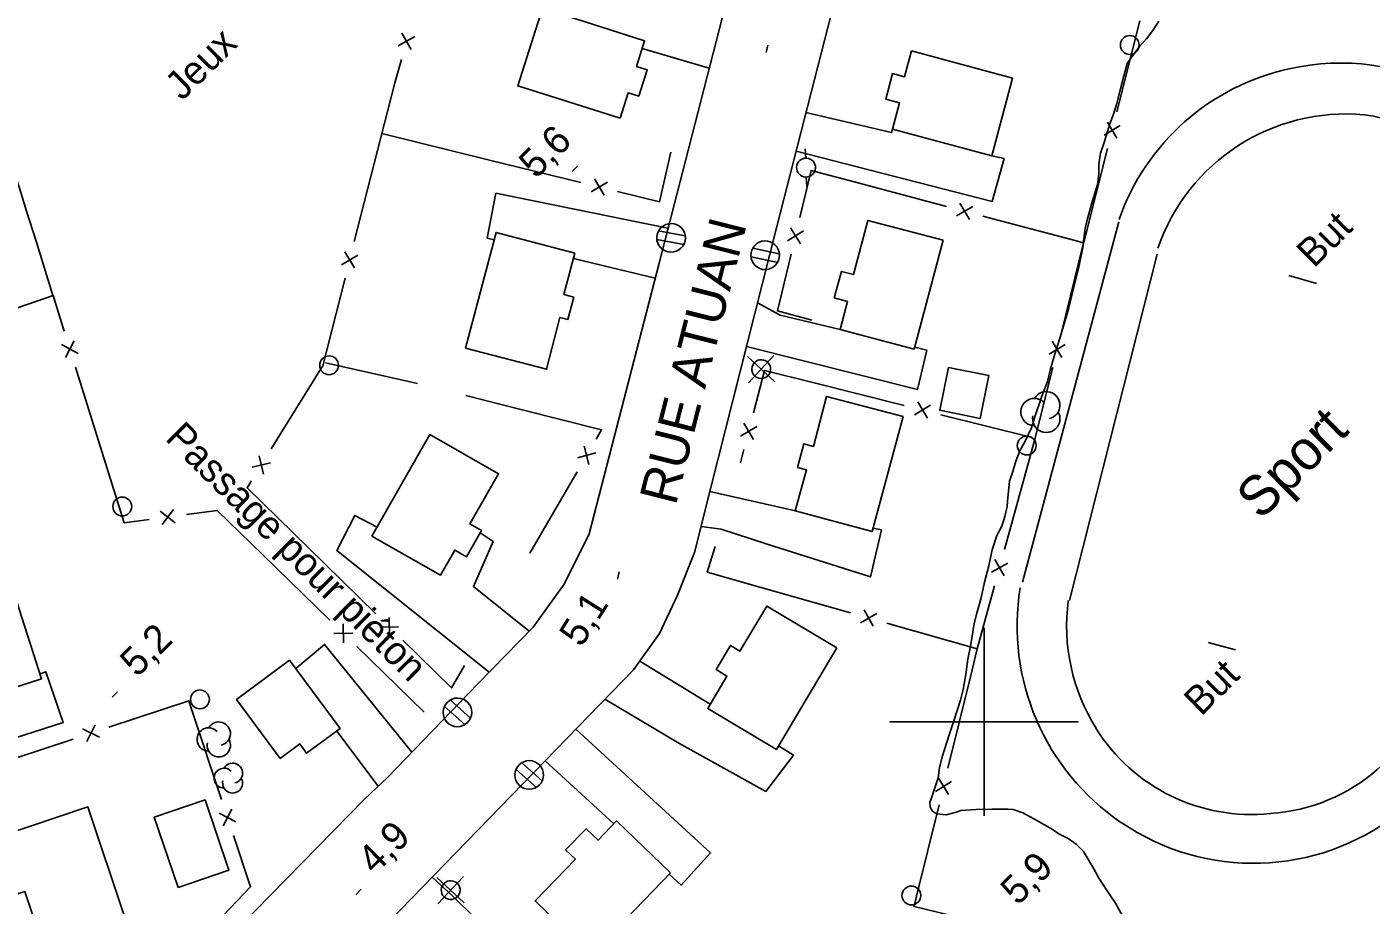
# Model space of a CAD drawing. Extents: x 381879 to 384696, y 5564785 to 5567594.
# Drawn here: x 382698.3 to 382841.1, y 5565380.5 to 5565473.8 of the extents above; entities that cross this region are included whole.
import ezdxf

# ---------------------------------------------------------------- set-up
doc = ezdxf.new("R2010")
doc.units = 0
for name, color, linetype in [('Niveau 19', 7, 'Continuous'), ('Niveau 2', 7, 'Continuous'), ('Niveau 21', 7, 'Continuous'), ('Niveau 22', 7, 'Continuous'), ('Niveau 3', 7, 'Continuous'), ('Niveau 31', 7, 'Continuous'), ('Niveau 36', 7, 'Continuous'), ('Niveau 37', 7, 'Continuous'), ('Niveau 44', 7, 'Continuous'), ('Niveau 56', 7, 'Continuous'), ('Niveau 61', 7, 'Continuous')]:
    doc.layers.add(name, color=color, linetype=linetype)

msp = doc.modelspace()

# ---------------------------------------------------------------- linework, layer by layer
at = {"layer": 'Niveau 19'}
for points in [[(382763.67, 5565471.54), (382770.81, 5565469.47)], [(382781.08, 5565464.75), (382790.16, 5565462.61), (382790.28, 5565462.99)], [(382800.82, 5565460.15), (382802.13, 5565459.87), (382800.86, 5565455.29), (382780.03, 5565460.63)], [(382747.95, 5565451.23), (382747.21, 5565451.41), (382748.15, 5565456.16), (382766.41, 5565452.45), (382766.42, 5565452.45)], [(382765.06, 5565447.16), (382756.37, 5565449.23)], [(382775.93, 5565444.51), (382778.33, 5565443.2), (382784.72, 5565441.69)], [(382792.63, 5565439.8), (382793.91, 5565439.5), (382792.92, 5565435.3), (382774.77, 5565439.88)], [(382770.88, 5565424.47), (382779.96, 5565422.44)], [(382735.51, 5565420.69), (382733.15, 5565421.93), (382731.25, 5565418.22), (382747.42, 5565405.29)], [(382788.2, 5565420.6), (382789.1, 5565420.4), (382787.93, 5565415.4), (382776.86, 5565418.93), (382772.07, 5565420.49), (382769.93, 5565420.76)], [(382751.68, 5565409.63), (382745.76, 5565414.37), (382747.86, 5565419.15), (382746.47, 5565420.07)], [(382739.2, 5565396.77), (382729.94, 5565408.23), (382726.87, 5565405.68)], [(382763.42, 5565406.46), (382770.91, 5565401.88)], [(382684.96, 5565394.41), (382702.18, 5565399.93), (382700.34, 5565405.32), (382699.72, 5565405.09)], [(382778.17, 5565397.44), (382779.77, 5565396.46), (382776.82, 5565392.62), (382767.56, 5565397.74), (382759.71, 5565402.4)], [(382731.24, 5565399.03), (382735.65, 5565393.18)], [(382756.62, 5565399.21), (382770.95, 5565386.07), (382767.82, 5565382.64), (382766.54, 5565383.81)], [(382760.68, 5565389.18), (382753.37, 5565395.86)], [(382741.38, 5565383.49), (382741.38, 5565383.49), (382743.58, 5565381.49)]]:
    msp.add_lwpolyline(points, dxfattribs=at)
at = {"layer": 'Niveau 2'}
for points in [[(382810.51, 5565450.36), (382810.59, 5565451.36), (382810.75, 5565452.43), (382810.99, 5565453.46), (382811.43, 5565455.02), (382812.06, 5565457.11), (382812.19, 5565458.19), (382812.18, 5565459.26), (382812.38, 5565460.42), (382812.71, 5565461.44), (382813.35, 5565463.55), (382813.75, 5565464.56), (382814.08, 5565465.6), (382814.5, 5565467.27), (382815.21, 5565469.96), (382815.51, 5565470.4), (382816.51, 5565471.76), (382817.26, 5565472.58), (382817.94, 5565473.45), (382818.57, 5565474.47)], [(382814.76, 5565379.33), (382813.97, 5565380.75), (382813.35, 5565381.63), (382812.2, 5565383.41), (382811.68, 5565384.37), (382810.55, 5565386.24), (382809.8, 5565387), (382808.94, 5565387.61), (382808.01, 5565388.07), (382807.08, 5565388.67), (382805.69, 5565389.5), (382804.13, 5565390.33), (382803.09, 5565390.69), (382802.53, 5565390.74), (382800.86, 5565390.74), (382799.16, 5565390.68), (382797.54, 5565390.57), (382797.05, 5565390.39), (382795.99, 5565390.14), (382794.96, 5565390.22), (382794.53, 5565390.5), (382794.26, 5565390.93), (382794.24, 5565391.45), (382794.43, 5565391.92), (382795.11, 5565394.04), (382795.27, 5565395.16), (382795.6, 5565396.39), (382796.29, 5565398.63), (382796.8, 5565400.1), (382797.5, 5565402.32), (382797.77, 5565403.44), (382798.06, 5565405.02), (382798.29, 5565406.65), (382798.58, 5565408.21), (382798.94, 5565410.44), (382799.22, 5565411.55), (382799.68, 5565413.18), (382800.06, 5565414.86), (382800.52, 5565416.59), (382800.86, 5565418.27), (382801.36, 5565419.82), (382801.88, 5565420.8), (382802.22, 5565421.82), (382802.45, 5565422.87), (382802.48, 5565423.4), (382802.69, 5565425.56), (382803.06, 5565426.6), (382803.37, 5565427.69), (382803.8, 5565428.81), (382804.37, 5565429.83), (382805.04, 5565431.25), (382805.35, 5565432.31), (382806.13, 5565434.61), (382806.75, 5565436.17), (382807.03, 5565437.36), (382807.52, 5565439.06), (382808.2, 5565441.24), (382808.96, 5565443.85), (382809.33, 5565445.35), (382810.02, 5565448.16), (382810.51, 5565450.36)]]:
    msp.add_lwpolyline(points, dxfattribs=at)
at = {"layer": 'Niveau 21'}
for points in [[(382736.84, 5565378.81), (382762.75, 5565405.53), (382765.51, 5565409.4), (382767.44, 5565413.45), (382769.23, 5565418), (382770.99, 5565424.91), (382777.98, 5565452.62), (382787.43, 5565489.58), (382788.25, 5565496.22), (382787.1, 5565503.63), (382785.24, 5565508.98), (382782.37, 5565514.83), (382778.89, 5565519.05), (382767.35, 5565530.18), (382735.67, 5565561.36)], [(382730.39, 5565550.67), (382767.83, 5565514.18), (382773, 5565508.93), (382774.93, 5565505.67), (382776.39, 5565500.71), (382776.99, 5565495.97), (382776.75, 5565491.78), (382774.09, 5565482.23), (382765.47, 5565448.74), (382758.05, 5565419.99), (382755.4, 5565414.64), (382752.11, 5565410.06), (382746.24, 5565404.09), (382736.62, 5565394.08), (382734.21, 5565391.84)], [(382734.21, 5565391.84), (382717.54, 5565374.77), (382712.17, 5565371.05), (382707.53, 5565369.06), (382699.65, 5565366.49), (382696.58, 5565366.97), (382693.99, 5565368.71), (382692.37, 5565372.29), (382686.7, 5565389.28), (382676.19, 5565420.31), (382666.83, 5565448.64), (382660.42, 5565467.72), (382659.08, 5565473.74), (382659.16, 5565480.09), (382661.82, 5565489.21), (382666.49, 5565497.49), (382676.36, 5565507.68), (382696.82, 5565528.64), (382716.35, 5565548.84)]]:
    msp.add_lwpolyline(points, dxfattribs=at)
at = {"layer": 'Niveau 3'}
for p, q in [((382776.84, 5565471.11), (382777.02, 5565471.89)), ((382756.23, 5565458.48), (382756.8, 5565459.05)), ((382761.07, 5565415.18), (382761.25, 5565415.95)), ((382707.37, 5565402.63), (382707.94, 5565403.2)), ((382733.25, 5565381.64), (382733.82, 5565382.21))]:
    msp.add_line(p, q, dxfattribs=at)
at = {"layer": 'Niveau 31'}
for points in [[(382761.35, 5565464.14), (382750.47, 5565467.58), (382753.08, 5565475.82), (382763.94, 5565472.38), (382763.08, 5565469.65), (382764.21, 5565469.29), (382763.32, 5565466.49), (382762.2, 5565466.84)], [(382792.28, 5565471.29), (382803.04, 5565468.39), (382800.82, 5565460.15), (382790.28, 5565462.99), (382791.03, 5565465.77), (382789.55, 5565466.17), (382790.28, 5565468.88), (382791.54, 5565468.54)], [(382795.65, 5565451.18), (382792.58, 5565439.61), (382784.72, 5565441.69), (382785.51, 5565444.68), (382784.09, 5565445.06), (382784.84, 5565447.87), (382786.13, 5565447.53), (382787.66, 5565453.29)], [(382744.91, 5565439.7), (382748.16, 5565452.01), (382756.52, 5565449.8), (382755.36, 5565445.41), (382756.42, 5565445.13), (382755.79, 5565442.74), (382754.94, 5565442.96), (382753.52, 5565437.47)], [(382796.22, 5565437.66), (382800.52, 5565436.79), (382799.6, 5565432.24), (382795.3, 5565433.11)], [(382791.4, 5565432.44), (382788.1, 5565420.22), (382779.95, 5565422.42), (382781.13, 5565426.79), (382780.19, 5565427.04), (382780.85, 5565429.53), (382781.87, 5565429.26), (382783.27, 5565434.58)], [(382734.97, 5565419.74), (382741.14, 5565430.54), (382748.43, 5565426.37), (382745.38, 5565421.03), (382746.61, 5565420.32), (382745.02, 5565417.55), (382743.77, 5565418.26), (382742.24, 5565415.58)], [(382695.97, 5565416.73), (382699.88, 5565404.58), (382691.71, 5565401.95), (382690.3, 5565406.32), (382689.35, 5565406.01), (382688.62, 5565408.26), (382689.5, 5565408.54), (382687.73, 5565414.1)], [(382784.37, 5565407.85), (382777.95, 5565397.08), (382770.64, 5565401.43), (382772.69, 5565404.87), (382771.55, 5565405.55), (382773.08, 5565408.12), (382774.07, 5565407.53), (382776.91, 5565412.3)], [(382726.23, 5565406.55), (382731.59, 5565399.29), (382728.03, 5565396.66), (382727.3, 5565397.65), (382725.23, 5565396.12), (382720.6, 5565402.38)], [(382704.78, 5565390.97), (382708.7, 5565379.33), (382699.98, 5565376.38), (382698.09, 5565381.99), (382697.34, 5565381.73), (382695.3, 5565387.77)], [(382714.37, 5565382.41), (382711.85, 5565389.88), (382717.25, 5565391.7), (382719.77, 5565384.23)], [(382766.69, 5565383.97), (382758.25, 5565375.22), (382752.3, 5565380.97), (382756.58, 5565385.4), (382755.55, 5565386.4), (382757.72, 5565388.65), (382758.99, 5565387.43), (382760.97, 5565389.48)]]:
    msp.add_lwpolyline(points, close=True, dxfattribs=at)
at = {"layer": 'Niveau 36'}
for p, q in [((382781.01, 5565460.88), (382781.06, 5565459.88)), ((382781.16, 5565456.88), (382781.12, 5565457.88)), ((382768.24, 5565451.63), (382765.39, 5565452.16)), ((382765.24, 5565451.25), (382768.09, 5565450.72)), ((382775.25, 5565449.42), (382778.08, 5565448.82)), ((382778.25, 5565449.72), (382775.42, 5565450.32)), ((382774.86, 5565438.84), (382777.77, 5565436.12)), ((382774.96, 5565436.03), (382777.68, 5565438.94)), ((382745.44, 5565400.41), (382743.27, 5565402.33)), ((382742.68, 5565401.63), (382744.85, 5565399.71)), ((382753.07, 5565393.75), (382750.89, 5565395.66)), ((382750.29, 5565394.95), (382752.47, 5565393.04)), ((382741.87, 5565383.48), (382744.78, 5565380.76)), ((382741.97, 5565380.67), (382744.69, 5565383.58))]:
    msp.add_line(p, q, dxfattribs=at)
for centre in [(382815.48, 5565471.92), (382730.42, 5565437.89), (382804.53, 5565429.36), (382708.45, 5565422.88), (382716.7, 5565402.39), (382792.28, 5565381.55)]:
    msp.add_circle(centre, 1, dxfattribs=at)
for centre, major_axis, ratio in [((382781.09, 5565458.89), (-0.05, -0.999), 0.999983), ((382766.75, 5565451.43), (0.04, 1.52), 0.999984), ((382776.74, 5565449.58), (-0.04, 1.52), 0.999983), ((382776.33, 5565437.48), (-0.048, -0.999), 0.999982), ((382744.06, 5565401.01), (0.02, 1.52), 0.999985), ((382751.68, 5565394.36), (-0.01, -1.52), 0.999982), ((382743.34, 5565382.12), (-0.048, -0.999), 0.999982)]:
    msp.add_ellipse(centre, major_axis=major_axis, ratio=ratio, dxfattribs=at)
at = {"layer": 'Niveau 37'}
for p, q in [((382739.52, 5565472.81), (382737.77, 5565471.83)), ((382739.13, 5565471.44), (382738.16, 5565473.19)), ((382813.1, 5565463.73), (382814.12, 5565462.01)), ((382812.75, 5565462.35), (382814.47, 5565463.38)), ((382759.98, 5565457.36), (382758.27, 5565456.32)), ((382758.6, 5565457.69), (382759.64, 5565455.98)), ((382798.44, 5565453.39), (382797.43, 5565455.13)), ((382797.07, 5565453.76), (382798.8, 5565454.76)), ((382780.82, 5565452.17), (382779.11, 5565451.12)), ((382780.49, 5565450.79), (382779.44, 5565452.5)), ((382733.47, 5565449.6), (382731.75, 5565448.58)), ((382733.12, 5565448.23), (382732.1, 5565449.95)), ((382703.76, 5565439.15), (382701.99, 5565440.08)), ((382703.34, 5565440.5), (382702.41, 5565438.72)), ((382806.91, 5565439.07), (382808.63, 5565440.11)), ((382807.25, 5565440.45), (382808.28, 5565438.73)), ((382794.32, 5565433.64), (382792.6, 5565432.61)), ((382792.95, 5565433.99), (382793.98, 5565432.27)), ((382774.12, 5565430.37), (382775.85, 5565431.39)), ((382774.48, 5565431.75), (382775.49, 5565430.02)), ((382723.45, 5565426.33), (382722.99, 5565428.28)), ((382758.74, 5565428.57), (382756.81, 5565428.06)), ((382758.03, 5565427.34), (382757.52, 5565429.28)), ((382724.2, 5565427.53), (382722.25, 5565427.08)), ((382712.48, 5565422.38), (382714.07, 5565421.16)), ((382713.89, 5565422.56), (382712.67, 5565420.97)), ((382800.78, 5565415.89), (382802.52, 5565416.88)), ((382801.15, 5565417.25), (382802.14, 5565415.51)), ((382736.8, 5565411.08), (382736.82, 5565409.08)), ((382788.61, 5565411.52), (382786.86, 5565410.54)), ((382787.25, 5565411.91), (382788.22, 5565410.16)), ((382732.93, 5565409.43), (382730.92, 5565409.4)), ((382731.91, 5565410.42), (382731.94, 5565408.41)), ((382737.81, 5565410.09), (382735.81, 5565410.07)), ((382705.58, 5565399.7), (382704.68, 5565397.91)), ((382704.24, 5565399.26), (382706.02, 5565398.36)), ((382794.84, 5565392.62), (382796.55, 5565393.66)), ((382795.18, 5565393.99), (382796.22, 5565392.28)), ((382720.52, 5565389.39), (382718.73, 5565390.29)), ((382720.08, 5565390.73), (382719.18, 5565388.94))]:
    msp.add_line(p, q, dxfattribs=at)
for points in [[(382816.56, 5565474.5), (382814.1, 5565464.81)], [(382735.57, 5565460.72), (382737.4, 5565467.91), (382738.1, 5565470.39)], [(382747.47, 5565459.7), (382736.03, 5565462.52)], [(382813.12, 5565460.93), (382810.66, 5565451.23)], [(382699.29, 5565451.06), (382698.28, 5565454.27), (382697.66, 5565456.24), (382696.3, 5565460.6)], [(382733.1, 5565451.03), (382735.57, 5565460.72)], [(382757.18, 5565457.32), (382747.47, 5565459.7)], [(382766.71, 5565460.53), (382765.53, 5565455.26), (382761.06, 5565456.36)], [(382780.43, 5565453.59), (382781.63, 5565458.58), (382786.34, 5565457.33)], [(382786.34, 5565457.33), (382796, 5565454.77)], [(382799.87, 5565453.75), (382809.54, 5565451.19)], [(382702.28, 5565441.52), (382701.09, 5565445.32), (382701.08, 5565445.32), (382699.32, 5565450.96), (382699.29, 5565451.06)], [(382810.66, 5565451.23), (382810.58, 5565450.91), (382808.25, 5565441.53)], [(382809.54, 5565451.19), (382810.58, 5565450.91)], [(382781.71, 5565442.69), (382778.05, 5565443.66), (382779.5, 5565449.7)], [(382729.54, 5565437.5), (382729.74, 5565437.82), (382732.12, 5565447.15)], [(382695.46, 5565443.35), (382701.09, 5565445.32)], [(382739.8, 5565435.94), (382730.05, 5565438.16)], [(382706.46, 5565428.16), (382703.47, 5565437.7)], [(382724.27, 5565429.01), (382729.54, 5565437.5)], [(382781.82, 5565436.05), (382776.67, 5565437.35), (382775.49, 5565432.82)], [(382807.29, 5565437.65), (382805.36, 5565429.9), (382804.83, 5565427.96)], [(382791.52, 5565433.61), (382781.82, 5565436.05)], [(382750.78, 5565433.2), (382744.95, 5565434.67)], [(382758.78, 5565430.04), (382759.36, 5565431.04), (382750.78, 5565433.2)], [(382805.1, 5565430.2), (382795.4, 5565432.64)], [(382711.29, 5565421.51), (382708.65, 5565421.16), (382706.46, 5565428.16)], [(382774.48, 5565428.95), (382774.11, 5565427.53)], [(382804.83, 5565427.96), (382802.18, 5565418.31)], [(382751.74, 5565417.94), (382756.77, 5565426.58)], [(382728.24, 5565418.48), (382721.71, 5565424.87), (382722.17, 5565425.61)], [(382723.33, 5565417.79), (382718.54, 5565422.46), (382715.26, 5565422.03)], [(382735.38, 5565411.48), (382728.24, 5565418.48)], [(382776.19, 5565414.31), (382770.6, 5565415.89), (382771.43, 5565418.64)], [(382730.49, 5565410.81), (382723.33, 5565417.79)], [(382785.81, 5565411.58), (382776.19, 5565414.31)], [(382801.12, 5565414.46), (382799.28, 5565407.76), (382798.55, 5565404.79)], [(382799.28, 5565407.76), (382789.66, 5565410.49)], [(382740.52, 5565401.04), (382733.36, 5565408.02)], [(382744.81, 5565405.98), (382743.42, 5565403.61), (382738.24, 5565408.68)], [(382798.55, 5565404.79), (382796.17, 5565395.08)], [(382715.85, 5565401.23), (382715.51, 5565402.24), (382707.03, 5565399.44)], [(382719, 5565391.74), (382715.85, 5565401.23)], [(382703.23, 5565398.18), (382693.74, 5565395.04)], [(382795.22, 5565391.19), (382792.84, 5565381.48)], [(382719.15, 5565379.42), (382722.08, 5565382.46), (382720.26, 5565387.94)], [(382743.58, 5565381.49), (382750.7, 5565374.47)], [(382792.84, 5565381.48), (382792.57, 5565380.38), (382801.19, 5565378.3)]]:
    msp.add_lwpolyline(points, dxfattribs=at)
at = {"layer": 'Niveau 44'}
for centre, radius, start, end in [((382806.61, 5565433.64), 1.45, 282.2692, 149.7262), ((382805.36, 5565432.92), 1.45, 44.1153, 269.8039), ((382806.61, 5565432.2), 1.45, 166.9368, 29.6212), ((382717.63, 5565398.13), 1.24, 44.1153, 269.8039), ((382718.7, 5565398.75), 1.24, 282.2692, 149.7262), ((382718.7, 5565397.51), 1.24, 166.9368, 29.6212), ((382719.26, 5565394.02), 1.06, 44.1153, 269.8039), ((382720.17, 5565394.55), 1.06, 282.2692, 149.7262), ((382720.17, 5565393.5), 1.06, 166.9368, 29.6212)]:
    msp.add_arc(centre, radius, start, end, dxfattribs=at)
at = {"layer": 'Niveau 56'}
for points in [[(382804.1, 5565414.85), (382814.33, 5565453.14)], [(382818.39, 5565449.7), (382809.07, 5565412.91)], [(382832.38, 5565447.42), (382835.33, 5565446.57)], [(382823.8, 5565408.45), (382826.71, 5565407.67)]]:
    msp.add_lwpolyline(points, dxfattribs=at)
for centre, radius, start, end in [((382837.64, 5565445.28), 24.66, 102.2461, 160.7961), ((382837.91, 5565445.49), 24.51, 21.6082, 102.9683), ((382838.44, 5565443.48), 21.11, 84.7237, 161.0608), ((382837.62, 5565444.76), 19.94, 349.5513, 82.0559), ((382828.78, 5565410.2), 25.27, 170.7977, 235.716), ((382829.36, 5565410.23), 20.59, 172.5144, 211.9802), ((382829.2, 5565409.36), 19.13, 273.6601, 348.5681), ((382828.39, 5565409.61), 19.45, 211.9541, 275.9844), ((382828.62, 5565409.89), 24.92, 235.6332, 307.8394)]:
    msp.add_arc(centre, radius, start, end, dxfattribs=at)
at = {"layer": 'Niveau 61'}
for points in [[(382800, 5565410), (382800, 5565400), (382800, 5565390)], [(382790, 5565400), (382800, 5565400), (382810, 5565400)]]:
    msp.add_lwpolyline(points, dxfattribs=at)

# ---------------------------------------------------------------- texts
at = {"layer": 'Niveau 21'}
msp.add_text('RUE ATUAN', height=4, rotation=75.823, dxfattribs=at).set_placement((382767.24, 5565422.89))
at = {"layer": 'Niveau 22'}
msp.add_text('Passage pour piéton', height=2.9996, rotation=315.1596, dxfattribs=at).set_placement((382712.89, 5565430.02))
at = {"layer": 'Niveau 3'}
for s, rotation, p in [('5,6', 44.7717, (382752.4, 5565457.61)), ('5,1', 57.6374, (382757.22, 5565407.83)), ('5,2', 44.7717, (382710.03, 5565404.65)), ('4,9  ', 44.7717, (382735.28, 5565383.68)), ('5,9  ', 44.7717, (382803.58, 5565380.4))]:
    msp.add_text(s, height=3, rotation=rotation, dxfattribs=at).set_placement(p)
at = {"layer": 'Niveau 56'}
for s, height, p in [('Jeux', 3, (382714.81, 5565465.91)), ('But', 3, (382835.05, 5565448.13)), ('Sport', 4.2, (382829.39, 5565421.34)), ('But', 3, (382823.06, 5565400.53))]:
    msp.add_text(s, height=height, rotation=44.7717, dxfattribs=at).set_placement(p)

doc.saveas('drawing.dxf')
